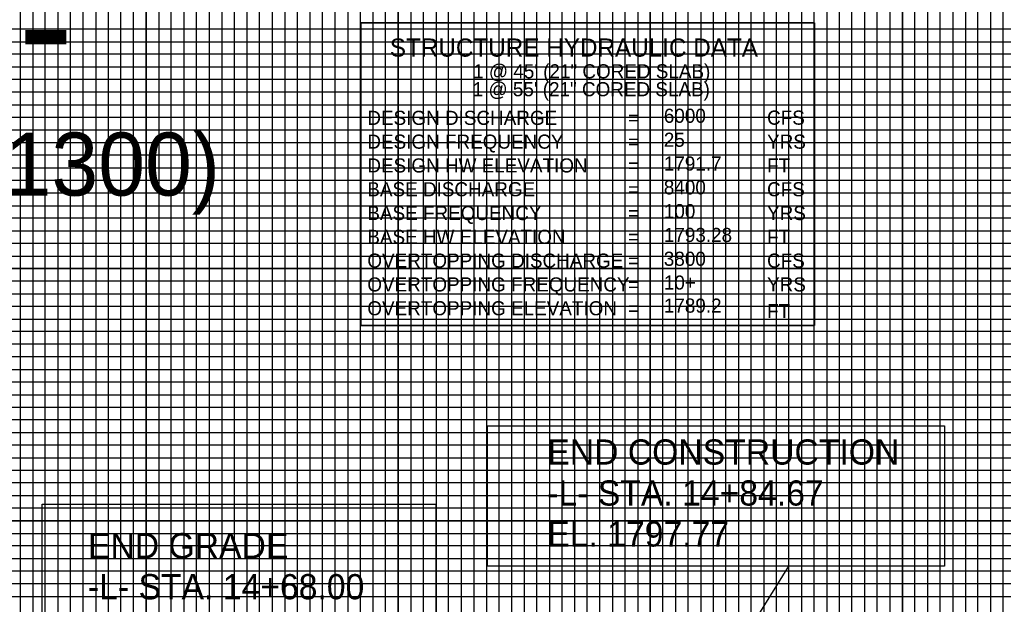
# Model space of a CAD drawing. Extents: x 572269 to 579912, y -56875 to -49627.
# Drawn here: x 574184.5 to 574574.7, y -53080.9 to -52849 of the extents above; entities that cross this region are included whole.
import ezdxf

# ---------------------------------------------------------------- set-up
doc = ezdxf.new("R2010")
doc.units = 0
for name, color, linetype in [('Prop Grid Mask', 7, 'Continuous'), ('Prop PFL Structure Hydraulic Data Label CELL', 7, 'Continuous'), ('Prop PFL Text', 7, 'Continuous'), ('Sheet Cutting Line CELL', 7, 'Continuous'), ('Sheet DOT Grid CELL', 7, 'Continuous'), ('Sheet Profile Grid Major CELL', 7, 'Continuous'), ('Sheet Profile Grid Middle CELL', 7, 'Continuous'), ('Sheet Profile Grid Minor CELL', 7, 'Continuous')]:
    doc.layers.add(name, color=color, linetype=linetype)

# ---------------------------------------------------------------- blocks, each defined once
blk = doc.blocks.new('PROFILE SHEET SINGLE')
at = {"layer": 'Sheet DOT Grid CELL'}
for p, q in [((7, 21), (7, 0.5)), ((8, 21), (8, 0.5)), ((9, 21), (9, 0.5)), ((10, 21), (10, 0.5)), ((11, 21), (11, 0.5)), ((12, 21), (12, 0.5)), ((13, 21), (13, 0.5)), ((14, 21), (14, 0.5)), ((0, 18.5), (25.999, 18.5)), ((0, 17.5), (30, 17.5)), ((0, 16.5), (30, 16.5)), ((0, 15.5), (30, 15.5))]:
    blk.add_line(p, q, dxfattribs=at)
at = {"layer": 'Sheet Profile Grid Major CELL'}
for points in [[(7, 21), (7, 0.5), (8, 0.5), (8, 21)], [(9, 21), (9, 0.5), (10, 0.5), (10, 21)], [(11, 21), (11, 0.5), (12, 0.5), (12, 21)], [(13, 21), (13, 0.5), (14, 0.5), (14, 21)], [(30, 17.5), (0, 17.5), (0, 18.5), (25.999, 18.5)], [(30, 15.5), (0, 15.5), (0, 16.5), (30, 16.5)]]:
    blk.add_lwpolyline(points, dxfattribs=at)
at = {"layer": 'Sheet Profile Grid Middle CELL'}
for points in [[(6.5, 21), (6.5, 0.5), (7.5, 0.5), (7.5, 21)], [(8.5, 21), (8.5, 0.5), (9.5, 0.5), (9.5, 21)], [(10.5, 21), (10.5, 0.5), (11.5, 0.5), (11.5, 21)], [(12.5, 21), (12.5, 0.5), (13.5, 0.5), (13.5, 21)], [(14.5, 21), (14.5, 0.5), (15.5, 0.5), (15.5, 21)], [(25.999, 19), (0, 19), (0, 17.999), (30, 17.999)], [(30, 17), (0, 17), (0, 16), (30, 16)], [(30, 15), (0, 15), (0, 14), (30, 14)]]:
    blk.add_lwpolyline(points, dxfattribs=at)
at = {"layer": 'Sheet Profile Grid Minor CELL'}
for p, q in [((29, 17.4), (1, 17.4)), ((1, 17.3), (29, 17.3)), ((29, 16.9), (1, 16.9))]:
    blk.add_line(p, q, dxfattribs=at)
for points in [[(7.1, 21), (7.1, 0.5), (7.2, 0.5), (7.2, 21)], [(7.3, 21), (7.3, 0.5), (7.4, 0.5), (7.4, 21)], [(7.6, 21), (7.6, 0.5), (7.9, 0.5), (7.9, 21)], [(8.1, 21), (8.1, 0.5), (8.2, 0.5), (8.2, 21)], [(8.3, 21), (8.3, 0.5), (8.4, 0.5), (8.4, 21)], [(8.6, 21), (8.6, 0.5), (8.7, 0.5), (8.7, 21)], [(8.8, 21), (8.8, 0.5), (8.9, 0.5), (8.9, 21)], [(9.1, 21), (9.1, 0.5), (9.2, 0.5), (9.2, 21)], [(9.3, 21), (9.3, 0.5), (9.4, 0.5), (9.4, 21)], [(9.6, 21), (9.6, 0.5), (9.7, 0.5), (9.7, 21)], [(9.8, 21), (9.8, 0.5), (9.9, 0.5), (9.9, 21)], [(10.1, 21), (10.1, 0.5), (10.2, 0.5), (10.2, 21)], [(10.3, 21), (10.3, 0.5), (10.4, 0.5), (10.4, 21)], [(10.6, 21), (10.6, 0.5)], [(7.7, 21), (7.7, 0.5), (7.8, 0.5), (7.8, 21)], [(10.7, 21), (10.7, 0.5), (10.8, 0.5), (10.8, 21), (10.9, 21), (10.9, 0.5), (11.1, 0.5), (11.1, 21), (11.2, 21), (11.2, 0.5), (11.3, 0.5), (11.3, 21), (11.4, 21), (11.4, 0.5)], [(11.6, 0.5), (11.6, 21)], [(11.7, 21), (11.7, 0.5), (11.8, 0.5), (11.8, 21)], [(11.9, 21), (11.9, 0.5), (12.1, 0.5), (12.1, 21)], [(12.2, 21), (12.2, 0.5), (12.2, 0.5), (12.3, 0.5), (12.3, 21)], [(12.4, 21), (12.4, 0.5), (12.6, 0.5), (12.6, 21)], [(12.7, 21), (12.7, 0.5), (12.8, 0.5), (12.8, 21)], [(12.9, 21), (12.9, 0.5), (13.1, 0.5), (13.1, 21)], [(13.2, 21), (13.2, 0.5), (13.3, 0.5), (13.3, 21)], [(13.4, 21), (13.4, 0.5), (13.6, 0.5), (13.6, 21)], [(13.7, 21), (13.7, 0.5), (13.8, 0.5), (13.8, 21)], [(13.9, 21), (13.9, 0.5), (14.1, 0.5), (14.1, 21)], [(14.2, 21), (14.2, 0.5), (14.3, 0.5), (14.3, 21)], [(14.4, 21), (14.4, 0.5), (14.6, 0.5), (14.6, 21)], [(14.7, 21), (14.7, 0.5), (14.8, 0.5), (14.8, 21)], [(7.7, 20.988), (7.7, 0.5), (7.8, 0.5), (7.8, 20.988)], [(25.999, 19.4), (1, 19.4), (1, 19.3), (25.999, 19.3)], [(25.999, 19.2), (1, 19.2), (1, 19.1), (25.999, 19.1)], [(25.999, 18.9), (1, 18.9), (1, 18.8), (25.999, 18.8)], [(25.999, 18.7), (1, 18.7), (1, 18.6), (25.999, 18.6)], [(25.999, 18.4), (1, 18.4), (1, 18.3), (25.999, 18.3)], [(29, 18.2), (1, 18.2), (1, 18.2), (1, 17.8), (29, 17.8)], [(1, 18.1), (29, 18.1)], [(29, 17.9), (1, 17.9)], [(29, 17.7), (1, 17.7), (1, 17.6), (29, 17.6)], [(29, 17.2), (1, 17.2), (1, 17.1), (29, 17.1)], [(29, 16.8), (1, 16.8), (1, 16.7), (29, 16.7)], [(29, 16.6), (1, 16.6)], [(1, 16.4), (29, 16.4)], [(29, 16.3), (1, 16.3), (1, 16.2), (29, 16.2)], [(29, 16.1), (1, 16.1), (1, 15.9), (29, 15.9)], [(29, 15.8), (1, 15.8), (1, 15.7), (29, 15.7)], [(29, 15.6), (1, 15.6), (1, 15.4), (29, 15.4)], [(29, 15.3), (1, 15.3), (1, 15.2), (29, 15.2)], [(29, 15.1), (1, 15.1), (1, 14.9), (29, 14.9)]]:
    blk.add_lwpolyline(points, dxfattribs=at)

msp = doc.modelspace()

# ---------------------------------------------------------------- linework, layer by layer
at = {"layer": 'Prop Grid Mask'}
for points in [[(574319.83, -52850.23), (574499.83, -52850.23), (574499.83, -52970.23), (574319.83, -52970.23)], [(574370.15, -53010.04), (574551.36, -53010.04), (574551.36, -53065.71), (574370.15, -53065.71)], [(574193.47, -53041.08), (574349.65, -53041.08), (574349.65, -53102.18), (574193.47, -53102.18)]]:
    msp.add_lwpolyline(points, close=True, dxfattribs=at)
at = {"layer": 'Prop PFL Structure Hydraulic Data Label CELL'}
msp.add_lwpolyline([(574319.83, -52970.23), (574499.83, -52970.23), (574499.83, -52850.23), (574319.83, -52850.23)], close=True, dxfattribs=at)
at = {"layer": 'Prop PFL Text'}
msp.add_line((574369.36, -53258.86), (574489.62, -53065.71), dxfattribs=at)

# ---------------------------------------------------------------- block references
at = {"layer": 'Sheet Cutting Line CELL', "xscale": 50, "yscale": 50}
msp.add_blockref('PROFILE SHEET SINGLE', (573834.69, -53822.71), dxfattribs=at)

# ---------------------------------------------------------------- texts
at = {"layer": 'Prop PFL Structure Hydraulic Data Label CELL'}
for s, height, p in [('STRUCTURE HYDRAULIC DATA', 7.2, (574331.37, -52863.63)), ('1 @ 45\' (21" CORED SLAB) ', 5.5999, (574364.43, -52872.24)), ('1 @ 55\' (21" CORED SLAB)', 5.5999, (574364.26, -52879.34)), ('6000', 5.6, (574440.07, -52889.87)), ('CFS', 5.6, (574481.02, -52890.62)), ('DESIGN DISCHARGE', 5.5999, (574322.45, -52890.7)), ('= ', 5.6, (574425.88, -52890.7)), ('DESIGN FREQUENCY', 5.5999, (574322.45, -52900.14)), ('= ', 5.6, (574425.88, -52900.14)), ('25', 5.6, (574440.07, -52899.39)), ('YRS', 5.6, (574481.02, -52900.14)), ('DESIGN HW ELEVATION', 5.5999, (574322.45, -52909.58)), ('1791.7', 5.6, (574440.07, -52908.83)), ('FT', 5.6, (574481.02, -52909.58)), ('= ', 5.6, (574425.88, -52909.58)), ('BASE DISCHARGE', 5.5999, (574322.45, -52919.02)), ('= ', 5.6, (574425.88, -52919.02)), ('8400', 5.6, (574440.07, -52918.27)), ('CFS', 5.6, (574481.02, -52919.02)), ('BASE FREQUENCY', 5.5999, (574322.45, -52928.46)), ('100', 5.6, (574440.07, -52927.71)), ('YRS', 5.6, (574481.02, -52928.46)), ('= ', 5.6, (574425.88, -52928.46)), ('1793.28', 5.6, (574440.07, -52937.15)), ('BASE HW ELEVATION', 5.5999, (574322.45, -52937.9)), ('= ', 5.6, (574425.88, -52937.9)), ('FT', 5.6, (574481.02, -52937.9)), ('OVERTOPPING DISCHARGE', 5.5999, (574322.45, -52947.34)), ('= ', 5.6, (574425.88, -52947.34)), ('3800', 5.6, (574440.07, -52946.59)), ('CFS', 5.6, (574481.02, -52947.34)), ('OVERTOPPING FREQUENCY', 5.5999, (574322.45, -52956.78)), ('10+', 5.6, (574440.07, -52956.03)), ('YRS', 5.6, (574481.02, -52956.78)), ('=', 5.6, (574425.88, -52956.78)), ('OVERTOPPING ELEVATION', 5.5999, (574322.45, -52966.22)), ('= ', 5.6, (574425.88, -52966.22)), ('1789.2', 5.6, (574440.07, -52965.18)), ('FT', 5.6, (574481.02, -52967.34))]:
    msp.add_text(s, height=height, rotation=360, dxfattribs=at).set_placement(p)
at = {"layer": 'Prop PFL Text'}
for s, height, p in [('-L-', 50, (574124.3, -52875.2)), ('(SR 1300)', 25, (574111.64, -52918.75)), ('END CONSTRUCTION', 10, (574393.83, -53025.44)), ('-L- STA. 14+84.67', 10, (574393.83, -53041.69)), ('EL. 1797.77', 10, (574393.83, -53057.94)), ('END GRADE', 10, (574211.61, -53062.62)), ('-L- STA. 14+68.00', 10, (574211.61, -53078.87))]:
    msp.add_text(s, height=height, dxfattribs=at).set_placement(p)

doc.saveas('drawing.dxf')
